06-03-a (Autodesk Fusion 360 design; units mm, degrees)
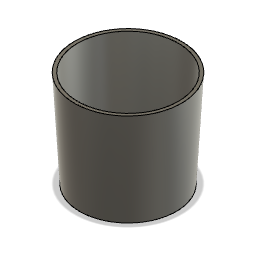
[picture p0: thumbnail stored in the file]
sketch "スケッチ" plane through (0, 0, 0) normal (0, 0, 1) x axis (1, 0, 0)
  line L1 (0, 45) -> (0, 0)
  line L2 (-25, 45) -> (0, 45)
  line L3 (-22.5, 0) -> (-25, 45)
  line L4 (0, 0) -> (-22.5, 0)
  point P1 (0, 0)
  point P2 (0, 0)
  point P3 (0, 45)
  point P5 (-22.5, 0)
  coincident P1 P2
  vertical L1
  perpendicular L1 L2
  perpendicular L1 L4
  dimension "d1" = 50
  dimension "d2" distance P2 P3 = 45
  dimension "d3" distance L1 P5 = 45
revolve "回転" sketch "スケッチ" AlongAngle 360
shell "シェル" innerThickness 1.5
offset_faces "面をオフセット" distance 1.5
